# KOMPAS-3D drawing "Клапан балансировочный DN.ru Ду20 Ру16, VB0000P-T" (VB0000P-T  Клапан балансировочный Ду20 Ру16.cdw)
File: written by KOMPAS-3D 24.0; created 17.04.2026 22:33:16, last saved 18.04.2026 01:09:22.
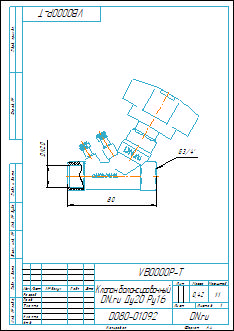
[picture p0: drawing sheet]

Document properties: Автор: tyuri; Форматы листов документа: A4; Полное имя файла: VB0000P-T Клапан балансировочный DN.ru Ду20 Ру16.m3d; Масса: 0.415; Наименование: Клапан балансировочный DN.ru Ду20 Ру16; Количество листов документа: 1; Примечание: D080-01092

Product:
- Body: Тело 2  | qty 1
    Масса: 0.925551
- Part/product: Клапан балансировочный DN.ru Ду20 Ру16  | designation VB0000P-T
    Масса: 0.415
    Раздел спецификации: Прочие изделия
    Примечание: D080-01092

Views: Вид 1, Местный разрез 1, Справа
Referenced files in D:\Аутсорс\VB0000P-T Клапан балансировочный статический DN.ru\DN20\: VB0000P-T Клапан балансировочный статический DN.ru Ду20 Ру16.m3d, VB0000P-T  Клапан балансировочный статический Ду15 Ру16.cdw
Referenced files in D:\Аутсорс\VB0000P-T Клапан балансировочный статический DN.ru\DN15\: VB0000P-T Клапан балансировочный статический Ду15 Ру16.m3d
Referenced files in E:\Работа\Зайцев\АУТСОРС\Диман\Балансировка\VB0000P-T Клапан балансировочный DN.ru Ду15-50 Ру16\DN20\: VB0000P-T Клапан балансировочный DN.ru Ду20 Ру16.m3d
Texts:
  VB0000P-T
  Клапан балансировочный
  DN.ru Ду20 Ру16
  Клапан балансировочный DN.ru Ду20 Ру16
  VB0000P-T Клапан балансировочный DN.ru Ду20 Ру16
Dimensions and other numbers on the sheet: 0; 3; 2; 4; 20; 80; 1:1; 1; 0,42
